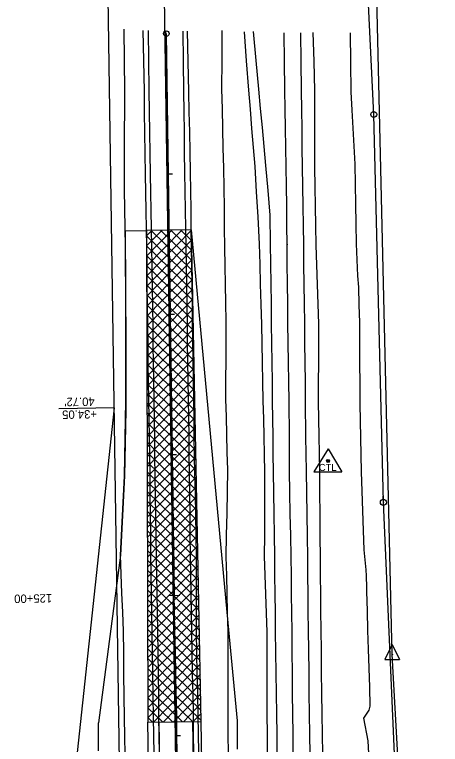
# Model space of a CAD drawing. Extents: x 1674300 to 1677920, y 225056 to 231852.
# Drawn here: x 1677253 to 1677556, y 229672 to 230191 of the extents above; entities that cross this region are included whole.
import ezdxf

# ---------------------------------------------------------------- set-up
doc = ezdxf.new("R2010")
doc.units = 0
for name, color, linetype in [('Default', 7, 'Continuous'), ('R_Axis', 7, 'Continuous'), ('R_Horz Alg', 7, 'Continuous'), ('R_Horz Alg Annot', 7, 'Continuous'), ('R_Proposed Const Limits_Cut', 7, 'Continuous'), ('R_Proposed Const Limits_Fill', 7, 'Continuous'), ('R_Proposed Road_Lane', 7, 'Continuous'), ('R_Proposed Road_Shoulder', 7, 'Continuous'), ('R_ROW', 7, 'Continuous'), ('R_ROW Annot', 7, 'Continuous'), ('S_DITCHLINE', 7, 'Continuous'), ('S_EDGE_PAVEMENT', 7, 'Continuous'), ('S_ELECTRIC_UTILITIES', 7, 'Continuous'), ('S_EXIST_ROW', 7, 'Continuous'), ('S_EXISTING_ALIGNMENT', 7, 'Continuous'), ('S_PAVEMENT_CROWN', 7, 'Continuous'), ('S_PRIMARY_CTL', 7, 'Continuous'), ('S_SHOULDER', 7, 'Continuous'), ('S_UTILITY_POLE', 7, 'Continuous'), ('S_UTL_PT_SYM', 7, 'Continuous')]:
    doc.layers.add(name, color=color, linetype=linetype)

msp = doc.modelspace()

# ---------------------------------------------------------------- linework, layer by layer
at = {"layer": 'Default'}
msp.add_line((1677360.58, 230177.65), (1677366.2, 229777.69), dxfattribs=at)
at = {"layer": 'R_Axis'}
for p, q in [((1677378.37, 230037.89), (1677346.5, 230037.44)), ((1677346.5, 230037.44), (1677347.47, 229687.42)), ((1677346.51, 230033.61), (1677350.29, 230037.49)), ((1677346.53, 230026.46), (1677357.37, 230037.59)), ((1677346.55, 230019.31), (1677364.44, 230037.69)), ((1677346.57, 230012.16), (1677371.52, 230037.79)), ((1677346.59, 230005.02), (1677378.37, 230037.66)), ((1677378.95, 230009.02), (1677349.71, 230037.49)), ((1677378.81, 230016.13), (1677356.77, 230037.59)), ((1677378.66, 230023.25), (1677363.84, 230037.68)), ((1677378.52, 230030.37), (1677370.91, 230037.78)), ((1677378.37, 230037.49), (1677377.97, 230037.88)), ((1677385.47, 229687.95), (1677378.37, 230037.89)), ((1677379.1, 230001.9), (1677346.51, 230033.63)), ((1677379.24, 229994.78), (1677346.53, 230026.63)), ((1677346.61, 229997.87), (1677378.51, 230030.64)), ((1677346.63, 229990.72), (1677378.65, 230023.62)), ((1677379.38, 229987.66), (1677346.55, 230019.63)), ((1677346.65, 229983.58), (1677378.8, 230016.6)), ((1677379.53, 229980.54), (1677346.56, 230012.63)), ((1677346.67, 229976.43), (1677378.94, 230009.58)), ((1677379.67, 229973.42), (1677346.58, 230005.64)), ((1677346.69, 229969.28), (1677379.08, 230002.56)), ((1677379.82, 229966.3), (1677346.6, 229998.64)), ((1677346.71, 229962.13), (1677379.22, 229995.54)), ((1677379.96, 229959.18), (1677346.62, 229991.64)), ((1677346.73, 229954.99), (1677379.37, 229988.51)), ((1677380.11, 229952.06), (1677346.64, 229984.64)), ((1677346.75, 229947.84), (1677379.51, 229981.49)), ((1677380.25, 229944.94), (1677346.66, 229977.65)), ((1677380.4, 229937.82), (1677346.68, 229970.65)), ((1677346.77, 229940.69), (1677379.65, 229974.47)), ((1677346.79, 229933.55), (1677379.79, 229967.45)), ((1677380.54, 229930.71), (1677346.7, 229963.65)), ((1677346.81, 229926.4), (1677379.94, 229960.43)), ((1677380.69, 229923.59), (1677346.72, 229956.65)), ((1677380.83, 229916.47), (1677346.74, 229949.66)), ((1677346.83, 229919.25), (1677380.08, 229953.41)), ((1677346.85, 229912.11), (1677380.22, 229946.39)), ((1677380.97, 229909.35), (1677346.76, 229942.66)), ((1677346.87, 229904.96), (1677380.36, 229939.37)), ((1677381.12, 229902.23), (1677346.78, 229935.66)), ((1677381.26, 229895.11), (1677346.8, 229928.66)), ((1677346.89, 229897.81), (1677380.51, 229932.34)), ((1677346.91, 229890.66), (1677380.65, 229925.32)), ((1677381.41, 229887.99), (1677346.82, 229921.67)), ((1677346.93, 229883.52), (1677380.79, 229918.3)), ((1677381.55, 229880.87), (1677346.84, 229914.67)), ((1677381.7, 229873.75), (1677346.86, 229907.67)), ((1677346.94, 229876.37), (1677380.93, 229911.28)), ((1677346.96, 229869.22), (1677381.08, 229904.26)), ((1677381.84, 229866.63), (1677346.88, 229900.68)), ((1677346.98, 229862.08), (1677381.22, 229897.24)), ((1677381.99, 229859.51), (1677346.9, 229893.68)), ((1677382.13, 229852.4), (1677346.92, 229886.68)), ((1677347, 229854.93), (1677381.36, 229890.22)), ((1677347.02, 229847.78), (1677381.51, 229883.2)), ((1677382.27, 229845.28), (1677346.94, 229879.68)), ((1677347.04, 229840.63), (1677381.65, 229876.18)), ((1677382.42, 229838.16), (1677346.96, 229872.69)), ((1677382.56, 229831.04), (1677346.97, 229865.69)), ((1677347.06, 229833.49), (1677381.79, 229869.15)), ((1677347.08, 229826.34), (1677381.93, 229862.13)), ((1677382.71, 229823.92), (1677346.99, 229858.69)), ((1677347.1, 229819.19), (1677382.08, 229855.11)), ((1677382.85, 229816.8), (1677347.01, 229851.69)), ((1677383, 229809.68), (1677347.03, 229844.7)), ((1677347.12, 229812.05), (1677382.22, 229848.09)), ((1677347.14, 229804.9), (1677382.36, 229841.07)), ((1677383.14, 229802.56), (1677347.05, 229837.7)), ((1677383.29, 229795.44), (1677347.07, 229830.7)), ((1677347.16, 229797.75), (1677382.5, 229834.05)), ((1677347.18, 229790.6), (1677382.65, 229827.03)), ((1677383.43, 229788.32), (1677347.09, 229823.7)), ((1677347.2, 229783.46), (1677382.79, 229820.01)), ((1677383.58, 229781.21), (1677347.11, 229816.71)), ((1677383.72, 229774.09), (1677347.13, 229809.71)), ((1677347.22, 229776.31), (1677382.93, 229812.98)), ((1677347.24, 229769.16), (1677383.07, 229805.96)), ((1677383.86, 229766.97), (1677347.15, 229802.71)), ((1677347.26, 229762.02), (1677383.22, 229798.94)), ((1677384.01, 229759.85), (1677347.17, 229795.71)), ((1677384.15, 229752.73), (1677347.19, 229788.72)), ((1677347.28, 229754.87), (1677383.36, 229791.92)), ((1677347.3, 229747.72), (1677383.5, 229784.9)), ((1677384.3, 229745.61), (1677347.21, 229781.72)), ((1677347.32, 229740.58), (1677383.64, 229777.88)), ((1677384.44, 229738.49), (1677347.23, 229774.72)), ((1677384.59, 229731.37), (1677347.25, 229767.73)), ((1677347.34, 229733.43), (1677383.79, 229770.86)), ((1677347.36, 229726.28), (1677383.93, 229763.84)), ((1677384.73, 229724.25), (1677347.27, 229760.73)), ((1677347.38, 229719.13), (1677384.07, 229756.82)), ((1677384.88, 229717.13), (1677347.29, 229753.73)), ((1677385.02, 229710.01), (1677347.31, 229746.73)), ((1677347.4, 229711.99), (1677384.21, 229749.79)), ((1677347.42, 229704.84), (1677384.36, 229742.77)), ((1677385.16, 229702.9), (1677347.33, 229739.74)), ((1677347.44, 229697.69), (1677384.5, 229735.75)), ((1677385.31, 229695.78), (1677347.35, 229732.74)), ((1677385.45, 229688.66), (1677347.37, 229725.74)), ((1677347.46, 229690.55), (1677384.64, 229728.73)), ((1677351.45, 229687.48), (1677384.78, 229721.71)), ((1677379.1, 229687.86), (1677347.38, 229718.74)), ((1677372.04, 229687.77), (1677347.4, 229711.75)), ((1677358.53, 229687.58), (1677384.93, 229714.69)), ((1677364.97, 229687.67), (1677347.42, 229704.75)), ((1677365.6, 229687.67), (1677385.07, 229707.67)), ((1677372.68, 229687.77), (1677385.21, 229700.65)), ((1677357.9, 229687.57), (1677347.44, 229697.75)), ((1677350.84, 229687.47), (1677347.46, 229690.75)), ((1677379.75, 229687.87), (1677385.35, 229693.62)), ((1677347.47, 229687.42), (1677385.47, 229687.95))]:
    msp.add_line(p, q, dxfattribs=at)
at = {"layer": 'R_Horz Alg'}
msp.add_line((1677377.01, 229008.91), (1677360.58, 230177.65), dxfattribs=at)
at = {"layer": 'R_Horz Alg Annot'}
for points in [[(1677364.99, 230077.7), (1677361.99, 230077.66)], [(1677366.39, 229977.71), (1677363.39, 229977.67)], [(1677367.8, 229877.72), (1677364.8, 229877.68)], [(1677362.2, 229777.64), (1677370.2, 229777.75)], [(1677370.61, 229677.74), (1677367.61, 229677.7)]]:
    msp.add_lwpolyline(points, dxfattribs=at)
msp.add_circle((1677360.58, 230177.65), 2, dxfattribs=at)
at = {"layer": 'R_Proposed Const Limits_Cut'}
msp.add_line((1677331.39, 230037.23), (1677346.5, 230037.44), dxfattribs=at)
for points in [[(1677331.39, 230037.23), (1677331.85, 229955.95), (1677331.75, 229909.6), (1677330.88, 229862.77), (1677328.06, 229806.45), (1677312.37, 229686.93)], [(1677312.36, 229666.92), (1677312.35, 229676.93), (1677312.37, 229686.93)]]:
    msp.add_lwpolyline(points, dxfattribs=at)
at = {"layer": 'R_Proposed Const Limits_Fill'}
msp.add_lwpolyline([(1677411.19, 229668.31), (1677411.16, 229678.31), (1677411.17, 229688.32), (1677404.47, 229758.23), (1677378.37, 230037.89)], dxfattribs=at)
at = {"layer": 'R_Proposed Road_Lane'}
for p, q in [((1677347.47, 229687.42), (1677385.47, 229687.95)), ((1677362.08, 229217.16), (1677355.47, 229687.53)), ((1677386.08, 229217.34), (1677379.47, 229687.87))]:
    msp.add_line(p, q, dxfattribs=at)
at = {"layer": 'R_Proposed Road_Shoulder'}
for p, q in [((1677350.73, 229455.59), (1677347.47, 229687.42)), ((1677388.73, 229456.13), (1677385.47, 229687.95))]:
    msp.add_line(p, q, dxfattribs=at)
at = {"layer": 'R_ROW'}
msp.add_line((1677293.32, 229626.65), (1677323.6, 229911.16), dxfattribs=at)
at = {"layer": 'R_ROW Annot'}
msp.add_line((1677323.6, 229911.16), (1677284.08, 229910.51), dxfattribs=at)
at = {"layer": 'S_DITCHLINE'}
for points in [[(1677331.21, 229664.23), (1677331.06, 229677.4), (1677330.9, 229690.57), (1677330.68, 229705.98), (1677330.46, 229721.38), (1677330.24, 229736.79), (1677330.02, 229752.2), (1677329.53, 229765.76), (1677329.04, 229779.32), (1677328.55, 229792.89), (1677328.06, 229806.45), (1677328.76, 229820.53), (1677329.47, 229834.61), (1677330.17, 229848.69), (1677330.88, 229862.77), (1677331.13, 229876.15), (1677331.37, 229889.53), (1677331.62, 229902.91), (1677331.87, 229916.29), (1677331.86, 229929.51), (1677331.85, 229942.73), (1677331.85, 229955.95), (1677331.84, 229969.17), (1677331.77, 229983.33), (1677331.71, 229997.5), (1677331.64, 230011.66), (1677331.57, 230025.83), (1677331.36, 230039.38), (1677331.14, 230052.92), (1677330.93, 230066.47), (1677330.72, 230080.02), (1677330.81, 230094.19), (1677330.91, 230108.36), (1677331, 230122.53), (1677331.1, 230136.69), (1677330.84, 230158.74), (1677330.59, 230180.78)], [(1677404.72, 229665.16), (1677404.65, 229678.97), (1677404.58, 229692.77), (1677404.56, 229707.64), (1677404.53, 229722.52), (1677404.5, 229737.39), (1677404.48, 229752.27), (1677404.17, 229765.49), (1677403.85, 229778.72), (1677403.54, 229791.95), (1677403.23, 229805.18), (1677403.49, 229820.68), (1677403.74, 229836.18), (1677404, 229851.68), (1677404.26, 229867.18), (1677403.93, 229879.75), (1677403.6, 229892.32), (1677403.27, 229904.89), (1677402.94, 229917.46), (1677403.01, 229931.27), (1677403.07, 229945.08), (1677403.14, 229958.9), (1677403.2, 229972.71), (1677402.97, 229985.88), (1677402.74, 229999.05), (1677402.5, 230012.22), (1677402.27, 230025.39), (1677402.05, 230039.57), (1677401.84, 230053.74), (1677401.62, 230067.91), (1677401.4, 230082.09), (1677401.08, 230096.1), (1677400.77, 230110.11), (1677400.46, 230124.12), (1677400.14, 230138.12), (1677400.22, 230159.03), (1677400.3, 230179.93)], [(1677505.04, 229655.77), (1677504.24, 229674.27), (1677501.06, 229690.37), (1677504.91, 229695.99), (1677505.67, 229698.92), (1677505.25, 229712.38), (1677504.83, 229725.85), (1677504.41, 229739.31), (1677503.99, 229752.78), (1677503.62, 229766.63), (1677503.26, 229780.47), (1677503.28, 229783.38), (1677502.86, 229791.52), (1677502.67, 229795.84), (1677501.35, 229810.13), (1677500.87, 229824.02), (1677500.39, 229837.91), (1677499.91, 229851.79), (1677499.43, 229865.68), (1677498.96, 229889.9), (1677498.48, 229914.12), (1677498.4, 229928.6), (1677498.32, 229943.07), (1677498.24, 229957.55), (1677498.15, 229972.03), (1677497.82, 229984.63), (1677497.5, 229997.24), (1677496.84, 230005.18), (1677495.94, 230027.94), (1677495.69, 230042.13), (1677495.43, 230056.31), (1677495.18, 230070.5), (1677494.92, 230084.69), (1677494.21, 230097.55), (1677493.5, 230110.4), (1677492.78, 230123.26), (1677492.07, 230136.12), (1677491.86, 230157.13), (1677491.64, 230178.15)]]:
    msp.add_lwpolyline(points, dxfattribs=at)
at = {"layer": 'S_EDGE_PAVEMENT'}
for points in [[(1677355.78, 229665.09), (1677355.57, 229678.21), (1677355.36, 229691.32), (1677355.14, 229706.5), (1677354.93, 229721.67), (1677354.71, 229736.85), (1677354.49, 229752.02), (1677354.28, 229765.49), (1677354.07, 229778.96), (1677353.86, 229792.42), (1677353.65, 229805.89), (1677353.42, 229820.19), (1677353.19, 229834.49), (1677352.96, 229848.79), (1677352.73, 229863.09), (1677352.52, 229876.59), (1677352.3, 229890.09), (1677352.09, 229903.59), (1677351.87, 229917.09), (1677351.68, 229930.08), (1677351.49, 229943.07), (1677351.3, 229956.05), (1677351.11, 229969.04), (1677350.87, 229983.23), (1677350.64, 229997.42), (1677350.41, 230011.61), (1677350.17, 230025.8), (1677349.96, 230038.73), (1677349.75, 230051.65), (1677349.53, 230064.58), (1677349.32, 230077.5), (1677349.1, 230092.44), (1677348.88, 230107.37), (1677348.66, 230122.31), (1677348.45, 230137.24), (1677348.14, 230158.56), (1677347.83, 230179.87)], [(1677380.24, 229665.39), (1677380.02, 229678.98), (1677379.81, 229692.57), (1677379.56, 229707.33), (1677379.31, 229722.08), (1677379.07, 229736.83), (1677378.82, 229751.59), (1677378.56, 229765.13), (1677378.3, 229778.66), (1677378.04, 229792.2), (1677377.78, 229805.74), (1677377.62, 229820.28), (1677377.45, 229834.83), (1677377.29, 229849.38), (1677377.12, 229863.92), (1677376.94, 229877.3), (1677376.76, 229890.67), (1677376.58, 229904.05), (1677376.4, 229917.43), (1677376.18, 229930.95), (1677375.96, 229944.47), (1677375.75, 229957.99), (1677375.53, 229971.51), (1677375.32, 229985.01), (1677375.1, 229998.52), (1677374.89, 230012.02), (1677374.67, 230025.53), (1677374.45, 230038.85), (1677374.24, 230052.16), (1677374.02, 230065.48), (1677373.8, 230078.8), (1677373.62, 230093.23), (1677373.43, 230107.65), (1677373.24, 230122.08), (1677373.05, 230136.51), (1677372.76, 230158), (1677372.47, 230179.48)], [(1677439.48, 229664.28), (1677439.31, 229678.67), (1677439.15, 229693.05), (1677438.94, 229707.77), (1677438.74, 229722.49), (1677438.53, 229737.21), (1677438.32, 229751.94), (1677438.17, 229765.36), (1677438.02, 229778.79), (1677437.87, 229792.22), (1677437.72, 229805.65), (1677437.49, 229820.65), (1677437.27, 229835.66), (1677437.04, 229850.66), (1677436.82, 229865.66), (1677436.66, 229878.26), (1677436.51, 229890.86), (1677436.35, 229903.45), (1677436.19, 229916.05), (1677436.02, 229929.77), (1677435.84, 229943.49), (1677435.67, 229957.21), (1677435.49, 229970.93), (1677435.31, 229985.17), (1677435.12, 229999.41), (1677434.93, 230013.66), (1677434.75, 230027.9), (1677434.4, 230048.48), (1677432.92, 230066.08), (1677431.44, 230083.69), (1677430.17, 230097.26), (1677428.91, 230110.84), (1677427.65, 230124.42), (1677426.39, 230138), (1677424.5, 230158.55), (1677422.6, 230179.09)], [(1677462.89, 229664.39), (1677462.69, 229678.82), (1677462.49, 229693.25), (1677462.29, 229708.26), (1677462.1, 229723.27), (1677461.9, 229738.28), (1677461.71, 229753.29), (1677461.57, 229766.11), (1677461.43, 229778.93), (1677461.29, 229791.75), (1677461.15, 229804.57), (1677460.91, 229819.98), (1677460.67, 229835.38), (1677460.43, 229850.78), (1677460.2, 229866.19), (1677459.91, 229890.83), (1677459.61, 229915.48), (1677459.47, 229929.46), (1677459.32, 229943.44), (1677459.17, 229957.42), (1677459.02, 229971.4), (1677458.84, 229985.32), (1677458.65, 229999.25), (1677458.46, 230013.17), (1677458.28, 230027.1), (1677458.07, 230041.01), (1677457.86, 230054.92), (1677457.66, 230068.84), (1677457.45, 230082.75), (1677457.28, 230096.37), (1677457.12, 230109.99), (1677456.95, 230123.61), (1677456.79, 230137.23), (1677456.5, 230157.78), (1677456.21, 230178.33)]]:
    msp.add_lwpolyline(points, dxfattribs=at)
at = {"layer": 'S_ELECTRIC_UTILITIES'}
for p, q in [((1677508.13, 230120.1), (1677495.31, 230388.72)), ((1677514.95, 229844), (1677508.13, 230120.1)), ((1677525.77, 229595.69), (1677514.95, 229844))]:
    msp.add_line(p, q, dxfattribs=at)
at = {"layer": 'S_EXIST_ROW'}
for p, q in [((1677337.07, 229010.49), (1677299.88, 231497.46)), ((1677521.25, 229735.57), (1677507.28, 230335.43)), ((1677521.27, 229742.66), (1677515.98, 229732.03)), ((1677521.27, 229742.66), (1677526.5, 229732.03)), ((1677515.98, 229732.03), (1677526.5, 229732.03)), ((1677521.25, 229735.57), (1677521.25, 229735.57)), ((1677555.5, 229117.02), (1677521.25, 229735.57))]:
    msp.add_line(p, q, dxfattribs=at)
for radius in [0.18, 0.09]:
    msp.add_circle((1677521.25, 229735.57), radius, dxfattribs=at)
at = {"layer": 'S_EXISTING_ALIGNMENT'}
msp.add_line((1677375.22, 229134.43), (1677343.44, 231259.98), dxfattribs=at)
at = {"layer": 'S_PAVEMENT_CROWN'}
for points in [[(1677368.27, 229665.24), (1677368.12, 229678.74), (1677367.96, 229692.25), (1677367.65, 229707.17), (1677367.34, 229722.09), (1677367.03, 229737.01), (1677366.71, 229751.93), (1677366.48, 229765.43), (1677366.24, 229778.94), (1677366, 229792.45), (1677365.77, 229805.96), (1677365.61, 229820.3), (1677365.44, 229834.63), (1677365.28, 229848.97), (1677365.12, 229863.3), (1677364.85, 229876.81), (1677364.57, 229890.32), (1677364.3, 229903.83), (1677364.03, 229917.33), (1677363.9, 229930.66), (1677363.77, 229943.99), (1677363.64, 229957.32), (1677363.52, 229970.66), (1677363.28, 229984.42), (1677363.05, 229998.19), (1677362.82, 230011.96), (1677362.58, 230025.73), (1677362.37, 230038.89), (1677362.16, 230052.06), (1677361.94, 230065.22), (1677361.73, 230078.38), (1677361.51, 230093), (1677361.29, 230107.61), (1677361.07, 230122.23), (1677360.85, 230136.85), (1677360.51, 230158.2), (1677360.17, 230179.56)], [(1677450.85, 229664.49), (1677450.7, 229678.91), (1677450.55, 229693.34), (1677450.43, 229707.97), (1677450.3, 229722.61), (1677450.18, 229737.24), (1677450.05, 229751.88), (1677449.88, 229765.19), (1677449.7, 229778.5), (1677449.53, 229791.81), (1677449.35, 229805.12), (1677449.06, 229820.43), (1677448.77, 229835.75), (1677448.48, 229851.06), (1677448.19, 229866.38), (1677448.08, 229891.04), (1677447.97, 229915.7), (1677447.75, 229929.65), (1677447.52, 229943.6), (1677447.29, 229957.55), (1677447.06, 229971.49), (1677446.9, 229985.56), (1677446.74, 229999.63), (1677446.57, 230013.7), (1677446.41, 230027.77), (1677446.59, 230027.36), (1677446.39, 230041.25), (1677446.2, 230055.13), (1677446.01, 230069.02), (1677445.82, 230082.9), (1677445.58, 230096.59), (1677445.34, 230110.28), (1677445.09, 230123.96), (1677444.85, 230137.65), (1677444.62, 230157.91), (1677444.39, 230178.17)]]:
    msp.add_lwpolyline(points, dxfattribs=at)
at = {"layer": 'S_PRIMARY_CTL'}
for p, q in [((1677475.64, 229882.09), (1677465.61, 229865.57)), ((1677475.64, 229882.09), (1677485.47, 229865.57)), ((1677465.61, 229865.57), (1677485.47, 229865.57))]:
    msp.add_line(p, q, dxfattribs=at)
for radius in [1.04, 0.609, 0.344]:
    msp.add_circle((1677475.64, 229873.39), radius, dxfattribs=at)
at = {"layer": 'S_SHOULDER'}
for points in [[(1677351.93, 229664.86), (1677351.74, 229677.91), (1677351.54, 229690.95), (1677351.3, 229706.22), (1677351.06, 229721.48), (1677350.82, 229736.74), (1677350.58, 229752.01), (1677350.35, 229765.39), (1677350.12, 229778.77), (1677349.89, 229792.16), (1677349.65, 229805.54), (1677349.5, 229819.92), (1677349.34, 229834.31), (1677349.19, 229848.69), (1677349.04, 229863.07), (1677348.81, 229876.61), (1677348.59, 229890.14), (1677348.37, 229903.68), (1677348.14, 229917.22), (1677347.94, 229930.05), (1677347.74, 229942.88), (1677347.55, 229955.71), (1677347.35, 229968.54), (1677347.18, 229982.82), (1677347.02, 229997.09), (1677346.85, 230011.36), (1677346.69, 230025.63), (1677346.48, 230038.61), (1677346.26, 230051.59), (1677346.05, 230064.56), (1677345.84, 230077.54), (1677345.62, 230092.31), (1677345.39, 230107.08), (1677345.17, 230121.84), (1677344.95, 230136.61), (1677344.5, 230158.22), (1677344.05, 230179.83)], [(1677383.67, 229665.5), (1677383.46, 229679.08), (1677383.25, 229692.66), (1677382.94, 229707.39), (1677382.63, 229722.11), (1677382.33, 229736.83), (1677382.02, 229751.55), (1677382.05, 229765.07), (1677382.08, 229778.59), (1677382.11, 229792.11), (1677382.14, 229805.64), (1677381.83, 229820.25), (1677381.52, 229834.86), (1677381.21, 229849.48), (1677380.9, 229864.09), (1677380.7, 229877.47), (1677380.49, 229890.84), (1677380.29, 229904.22), (1677380.09, 229917.59), (1677379.89, 229931.11), (1677379.69, 229944.63), (1677379.5, 229958.15), (1677379.3, 229971.66), (1677379.11, 229985.17), (1677378.92, 229998.67), (1677378.73, 230012.17), (1677378.54, 230025.67), (1677378.35, 230039.03), (1677378.16, 230052.4), (1677377.97, 230065.76), (1677377.78, 230079.12), (1677377.49, 230093.39), (1677377.2, 230107.67), (1677376.92, 230121.94), (1677376.63, 230136.21), (1677376.18, 230157.83), (1677375.72, 230179.44)], [(1677432.65, 229664.07), (1677432.43, 229678.56), (1677432.2, 229693.05), (1677432.23, 229707.68), (1677432.26, 229722.31), (1677432.29, 229736.93), (1677432.31, 229751.56), (1677431.86, 229765.09), (1677431.41, 229778.62), (1677430.96, 229792.15), (1677430.51, 229805.69), (1677430.54, 229820.62), (1677430.58, 229835.55), (1677430.62, 229850.48), (1677430.65, 229865.41), (1677430.38, 229878.09), (1677430.11, 229890.77), (1677429.84, 229903.45), (1677429.57, 229916.13), (1677429.28, 229929.76), (1677428.99, 229943.4), (1677428.69, 229957.03), (1677428.4, 229970.66), (1677428.02, 229984.96), (1677427.64, 229999.26), (1677427.26, 230013.56), (1677426.88, 230027.85), (1677425.89, 230047.2), (1677424.8, 230065.07), (1677423.71, 230082.95), (1677422.58, 230096.59), (1677421.45, 230110.23), (1677420.33, 230123.86), (1677419.2, 230137.5), (1677417.66, 230158.25), (1677416.12, 230179)], [(1677471.85, 229664.55), (1677471.66, 229678.81), (1677471.46, 229693.07), (1677471.26, 229708.16), (1677471.06, 229723.25), (1677470.86, 229738.34), (1677470.65, 229753.43), (1677470.54, 229766.16), (1677470.43, 229778.89), (1677470.32, 229791.62), (1677470.2, 229804.35), (1677470.09, 229819.88), (1677469.98, 229835.41), (1677469.87, 229850.95), (1677469.75, 229866.48), (1677469.3, 229890.98), (1677468.85, 229915.48), (1677468.92, 229929.35), (1677468.98, 229943.22), (1677469.04, 229957.09), (1677469.1, 229970.96), (1677468.6, 229984.96), (1677468.11, 229998.97), (1677467.61, 230012.97), (1677467.12, 230026.97), (1677466.89, 230040.87), (1677466.66, 230054.77), (1677466.44, 230068.67), (1677466.21, 230082.57), (1677466.22, 230096.23), (1677466.22, 230109.9), (1677466.23, 230123.56), (1677466.24, 230137.23), (1677465.63, 230157.79), (1677465.02, 230178.35)]]:
    msp.add_lwpolyline(points, dxfattribs=at)
at = {"layer": 'S_UTILITY_POLE'}
for p, q in [((1677508.01, 230122.24), (1677508.01, 230124.35)), ((1677514.83, 229846.14), (1677514.83, 229848.25))]:
    msp.add_line(p, q, dxfattribs=at)
for centre in [(1677508.13, 230120.1), (1677514.95, 229844)]:
    msp.add_circle(centre, 2.13, dxfattribs=at)
at = {"layer": 'S_UTL_PT_SYM'}
for points in [[(1677508.13, 230120.1), (1677508.13, 230120.15), (1677508.13, 230120.1), (1677508.08, 230120.1), (1677508.13, 230120.1), (1677508.13, 230120.05), (1677508.13, 230120.1), (1677508.18, 230120.1)], [(1677514.95, 229844), (1677514.95, 229844.05), (1677514.95, 229844), (1677514.9, 229844), (1677514.95, 229844), (1677514.95, 229843.95), (1677514.95, 229844), (1677515, 229844)]]:
    msp.add_lwpolyline(points, dxfattribs=at)

# ---------------------------------------------------------------- texts
at = {"layer": 'R_Horz Alg Annot'}
msp.add_text('125+00', height=6, rotation=180.8056, dxfattribs=at).set_placement((1677279.33, 229778.63))
at = {"layer": 'R_ROW Annot'}
for s, p in [("40.72'", (1677309.58, 229918.67)), ('+34.05', (1677311.2, 229909.7))]:
    msp.add_text(s, height=6, rotation=180.9497, dxfattribs=at).set_placement(p)
at = {"layer": 'S_PRIMARY_CTL'}
msp.add_text('CTL', height=5, rotation=360, dxfattribs=at).set_placement((1677469.06, 229866.31))

doc.saveas('drawing.dxf')
